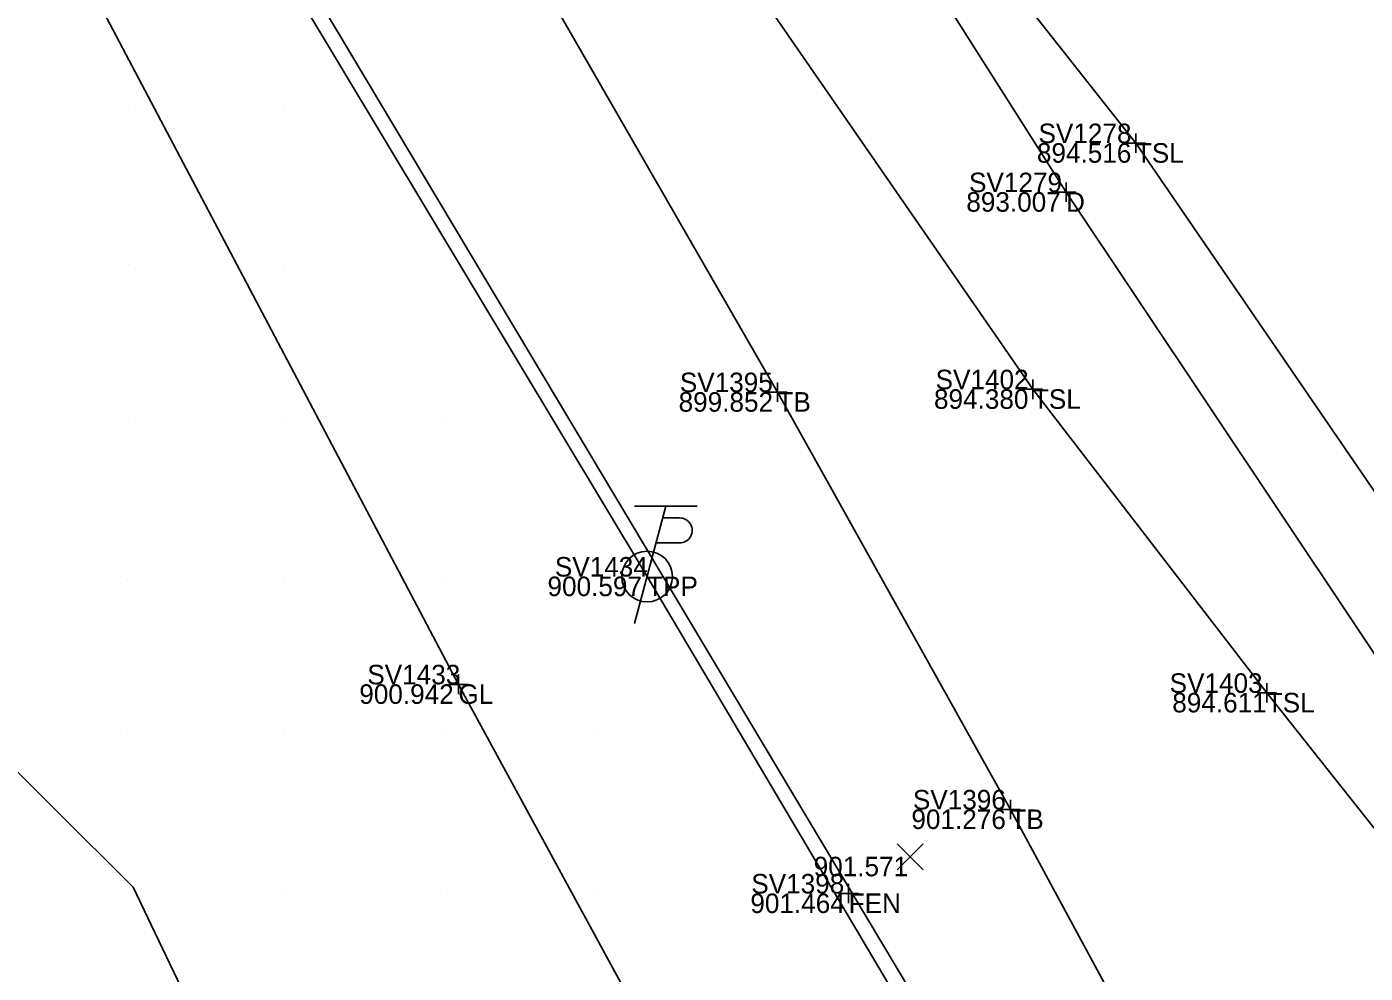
# Model space of a CAD drawing. Extents: x 1918148 to 1919797, y 624701 to 627089.
# Drawn here: x 1918866.3 to 1918934.8, y 625511 to 625559.4 of the extents above; entities that cross this region are included whole.
import ezdxf

# ---------------------------------------------------------------- set-up
doc = ezdxf.new("R2010")
doc.units = 0
for name, color, linetype in [('DR_X_Ditch', 7, 'Continuous'), ('DT_X_Terrain_Boundary', 7, 'Continuous'), ('Ground Shots', 7, 'Continuous'), ('RD_X_Fence', 7, 'Continuous'), ('SV_X_Random_Point', 7, 'Continuous'), ('SV_X_Shot_Marker', 7, 'Continuous'), ('SV_X_Text_Comment', 7, 'Continuous'), ('SV_X_Text_Elevation', 7, 'Continuous'), ('SV_X_Text_Name', 7, 'Continuous'), ('SV_X_Toe_of_Slope', 7, 'Continuous'), ('SV_X_Top_of_Bank', 7, 'Continuous'), ('UT_X_Gas', 7, 'Continuous'), ('UT_X_Misc_Cells', 7, 'Continuous'), ('UT_X_Overhead_Combined', 7, 'Continuous')]:
    doc.layers.add(name, color=color, linetype=linetype)

msp = doc.modelspace()

# ---------------------------------------------------------------- linework, layer by layer
at = {"layer": 'DR_X_Ditch'}
msp.add_lwpolyline([(1919022.603, 625413.065), (1918990.744, 625447.13), (1918963.473, 625485.28), (1918945.141, 625512.5), (1918919.457, 625550.942), (1918912.249, 625562.326), (1918904.466, 625574.16)], dxfattribs=at)
at = {"layer": 'DT_X_Terrain_Boundary'}
msp.add_lwpolyline([(1918796.762, 625701.528), (1918837.417, 625633.441), (1918839.502, 625611.203), (1918831.565, 625610.956), (1918831.449, 625603.209), (1918831.49, 625595.21), (1918831.786, 625587.295), (1918839.47, 625579.205), (1918839.493, 625571.214), (1918847.481, 625555.19), (1918855.45, 625539.209), (1918863.741, 625523.315), (1918871.72, 625515.381), (1918879.451, 625499.232)], dxfattribs=at)
at = {"layer": 'Ground Shots'}
for p, q in [((1918871.461, 625555.19), (1918871.461, 625555.19)), ((1918879.424, 625555.137), (1918879.424, 625555.137)), ((1918871.475, 625547.237), (1918871.475, 625547.237)), ((1918879.472, 625547.212), (1918879.472, 625547.212)), ((1918887.503, 625539.262), (1918887.503, 625539.262)), ((1918871.462, 625539.193), (1918871.462, 625539.193)), ((1918879.502, 625539.224), (1918879.502, 625539.224)), ((1918871.404, 625531.13), (1918871.404, 625531.13)), ((1918879.457, 625531.186), (1918879.457, 625531.186)), ((1918887.473, 625531.198), (1918887.473, 625531.198)), ((1918895.047, 625530.867), (1918895.047, 625530.867)), ((1918871.078, 625523.226), (1918871.078, 625523.226)), ((1918879.466, 625523.178), (1918879.466, 625523.178)), ((1918887.476, 625523.203), (1918887.476, 625523.203)), ((1918895.473, 625523.209), (1918895.473, 625523.209)), ((1918871.72, 625515.381), (1918871.72, 625515.381)), ((1918879.51, 625515.208), (1918879.51, 625515.208)), ((1918887.468, 625515.196), (1918887.468, 625515.196)), ((1918895.474, 625515.193), (1918895.474, 625515.193)), ((1918903.44, 625515.16), (1918903.44, 625515.16))]:
    msp.add_line(p, q, dxfattribs=at)
at = {"layer": 'RD_X_Fence'}
msp.add_lwpolyline([(1918745.788, 625786.434), (1918772.784, 625741.746), (1918796.762, 625701.528), (1918837.417, 625633.441), (1918845.82, 625619.995), (1919000.613, 625360.91)], dxfattribs=at)
at = {"layer": 'SV_X_Random_Point'}
for p, q in [((1918910.816, 625516.269), (1918912.15, 625517.605)), ((1918910.816, 625517.605), (1918912.15, 625516.269))]:
    msp.add_line(p, q, dxfattribs=at)
at = {"layer": 'SV_X_Shot_Marker'}
for p, q in [((1918923.03, 625553.95), (1918923.03, 625552.95)), ((1918922.53, 625553.45), (1918923.53, 625553.45)), ((1918923.03, 625553.45), (1918923.03, 625553.45)), ((1918918.957, 625550.942), (1918919.957, 625550.942)), ((1918919.457, 625551.442), (1918919.457, 625550.442)), ((1918919.457, 625550.942), (1918919.457, 625550.942)), ((1918917.761, 625541.356), (1918917.761, 625540.356)), ((1918904.187, 625540.709), (1918905.187, 625540.709)), ((1918904.687, 625541.209), (1918904.687, 625540.209)), ((1918904.687, 625540.709), (1918904.687, 625540.709)), ((1918917.261, 625540.856), (1918918.261, 625540.856)), ((1918917.761, 625540.856), (1918917.761, 625540.856)), ((1918888.363, 625526.258), (1918888.363, 625525.258)), ((1918887.863, 625525.758), (1918888.863, 625525.758)), ((1918888.363, 625525.758), (1918888.363, 625525.758)), ((1918929.731, 625525.822), (1918929.731, 625524.822)), ((1918929.231, 625525.322), (1918930.231, 625525.322)), ((1918929.731, 625525.322), (1918929.731, 625525.322)), ((1918916.608, 625519.856), (1918916.608, 625518.856)), ((1918916.108, 625519.356), (1918917.108, 625519.356)), ((1918916.608, 625519.356), (1918916.608, 625519.356)), ((1918908.333, 625515.556), (1918908.333, 625514.556)), ((1918907.833, 625515.056), (1918908.833, 625515.056)), ((1918908.333, 625515.056), (1918908.333, 625515.056))]:
    msp.add_line(p, q, dxfattribs=at)
at = {"layer": 'SV_X_Toe_of_Slope'}
for points in [[(1919029.642, 625418.083), (1918993.831, 625449.983), (1918967.662, 625488.104), (1918949.312, 625515.089), (1918923.03, 625553.45), (1918914.755, 625563.936), (1918909.609, 625577.644)], [(1918898.687, 625570.33), (1918902.545, 625562.887), (1918917.761, 625540.856), (1918929.731, 625525.322), (1918942.077, 625509.757), (1918961.186, 625481.315), (1918987.058, 625442.578), (1919013.134, 625409.902)]]:
    msp.add_lwpolyline(points, dxfattribs=at)
at = {"layer": 'SV_X_Top_of_Bank'}
msp.add_lwpolyline([(1918890.33, 625565.665), (1918904.687, 625540.709), (1918916.608, 625519.356), (1918928.233, 625497.866), (1918947.006, 625474.519), (1918970.062, 625431.738), (1918997.613, 625399.314)], dxfattribs=at)
at = {"layer": 'UT_X_Gas'}
msp.add_lwpolyline([(1918759.168, 625917.084), (1918754.306, 625900.243), (1918749.452, 625846.761), (1918748.461, 625829.004), (1918743.942, 625797.46), (1918743.006, 625773.569), (1918765.829, 625740.859), (1918795.68, 625692.777), (1918822.428, 625647.505), (1918838.928, 625617.602), (1918864.37, 625571.208), (1918888.363, 625525.758), (1918914.136, 625478.379), (1918935.187, 625439.317), (1918956.473, 625399.657), (1918975.299, 625371.47), (1919011.933, 625334.484), (1919018.035, 625313.569)], dxfattribs=at)
at = {"layer": 'UT_X_Misc_Cells'}
for p, q in [((1918898.981, 625534.872), (1918897.375, 625528.872)), ((1918900.581, 625534.872), (1918897.381, 625534.872)), ((1918898.821, 625534.272), (1918899.671, 625534.272)), ((1918898.48, 625532.997), (1918899.671, 625532.997))]:
    msp.add_line(p, q, dxfattribs=at)
msp.add_circle((1918898.018, 625531.272), 1.3, dxfattribs=at)
msp.add_arc((1918899.684, 625533.634), 0.638, 268.8767, 91.1233, dxfattribs=at)
at = {"layer": 'UT_X_Overhead_Combined'}
msp.add_lwpolyline([(1918749.028, 625800.122), (1918759.416, 625761.901), (1918898.018, 625531.272), (1919016.404, 625331.435)], dxfattribs=at)

# ---------------------------------------------------------------- texts
at = {"layer": 'SV_X_Text_Comment'}
for s, p in [('TSL', (1918923.03, 625552.45)), ('D', (1918919.457, 625549.942)), ('TB', (1918904.687, 625539.709)), ('TSL', (1918917.761, 625539.856)), ('TPP', (1918898.018, 625530.272)), ('GL', (1918888.363, 625524.758)), ('TSL', (1918929.731, 625524.322)), ('TB', (1918916.608, 625518.356)), ('FEN', (1918908.333, 625514.056))]:
    msp.add_text(s, height=1, dxfattribs=at).set_placement(p)
at = {"layer": 'SV_X_Text_Elevation'}
for s, p in [('894.516', (1918917.966, 625552.45)), ('893.007', (1918914.354, 625549.942)), ('899.852', (1918899.631, 625539.709)), ('894.380', (1918912.7, 625539.856)), ('900.597', (1918892.922, 625530.272)), ('900.942', (1918883.29, 625524.758)), ('894.611', (1918924.894, 625524.322)), ('901.276', (1918911.544, 625518.356)), ('901.571', (1918906.542, 625515.937)), ('901.464', (1918903.302, 625514.056))]:
    msp.add_text(s, height=1, dxfattribs=at).set_placement(p)
at = {"layer": 'SV_X_Text_Name'}
for s, p in [('SV1278', (1918918.048, 625553.45)), ('SV1279', (1918914.493, 625550.942)), ('SV1395', (1918899.693, 625540.709)), ('SV1402', (1918912.782, 625540.856)), ('SV1434', (1918893.298, 625531.272)), ('SV1433', (1918883.701, 625525.758)), ('SV1403', (1918924.758, 625525.322)), ('SV1396', (1918911.621, 625519.356)), ('SV1398', (1918903.351, 625515.056))]:
    msp.add_text(s, height=1, dxfattribs=at).set_placement(p)

doc.saveas('drawing.dxf')
